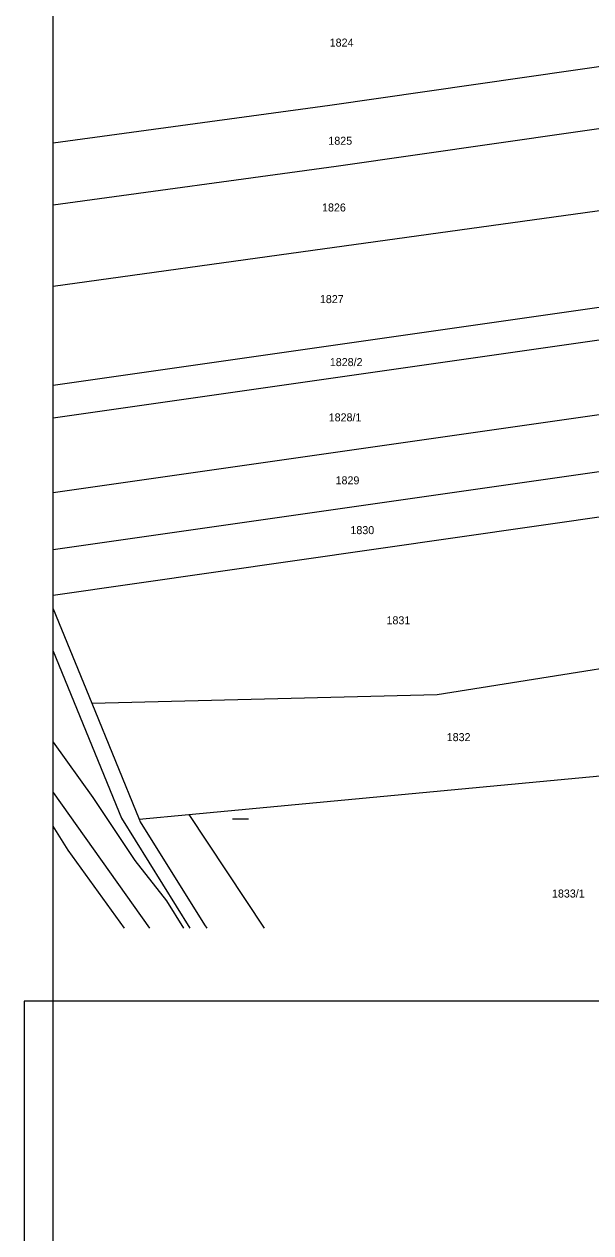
# Model space of a CAD drawing. Extents: x -601800 to -601487, y -1201912 to -1200862.
# Drawn here: x -601790.9 to -601649.2, y -1201385.7 to -1201083.7 of the extents above; entities that cross this region are included whole.
import ezdxf

# ---------------------------------------------------------------- set-up
doc = ezdxf.new("R2010")
doc.units = 0
for name, color, linetype in [('Hranice parcel', 7, 'Continuous'), ('Parcelní čísla', 7, 'Continuous'), ('u_strom', 7, 'Continuous'), ('x_rám', 7, 'Continuous')]:
    doc.layers.add(name, color=color, linetype=linetype)

msp = doc.modelspace()

# ---------------------------------------------------------------- linework, layer by layer
at = {"layer": 'Hranice parcel'}
for p, q in [((-601783.66, -1201173.9), (-601629.54, -1201151.87)), ((-601632.4, -1201160.49), (-601783.66, -1201182.11)), ((-601634.44, -1201179.47), (-601783.66, -1201200.8)), ((-601783.66, -1201214.97), (-601631.89, -1201193.28)), ((-601783.66, -1201226.33), (-601628.22, -1201204.11)), ((-601783.66, -1201229.79), (-601774, -1201253.38)), ((-601774, -1201253.38), (-601762.13, -1201282.35)), ((-601749.75, -1201281.18), (-601587.88, -1201265.89)), ((-601762.13, -1201282.35), (-601749.75, -1201281.18)), ((-601749.75, -1201281.18), (-601730.93, -1201309.6))]:
    msp.add_line(p, q, dxfattribs=at)
for points in [[(-601783.66, -1201113.35), (-601714.46, -1201103.92), (-601580.66, -1201084.64)], [(-601783.66, -1201128.79), (-601712.92, -1201119.14), (-601593.88, -1201102.11)], [(-601783.66, -1201149.13), (-601718.74, -1201140.14), (-601613.91, -1201125.63)], [(-601774, -1201253.38), (-601687.66, -1201251.2), (-601608.09, -1201238.51)], [(-601783.66, -1201240.35), (-601766.57, -1201282.06), (-601749.45, -1201309.6)], [(-601783.66, -1201263.06), (-601773.69, -1201276.89), (-601763.21, -1201292.63), (-601755.27, -1201302.75), (-601751.03, -1201309.6)], [(-601783.66, -1201275.7), (-601759.58, -1201309.6)], [(-601762.13, -1201282.35), (-601761.86, -1201283.01), (-601745.84, -1201308.76), (-601745.24, -1201309.6)], [(-601765.8, -1201309.6), (-601779.85, -1201290.08), (-601783.66, -1201284.08)]]:
    msp.add_lwpolyline(points, dxfattribs=at)
at = {"layer": 'u_strom'}
msp.add_lwpolyline([(-601790.89, -1201506.46), (-601590.84, -1201506.46), (-601590.84, -1201327.83), (-601790.89, -1201327.83)], close=True, dxfattribs=at)
at = {"layer": 'x_rám'}
msp.add_line((-601734.8, -1201282.35), (-601738.84, -1201282.35), dxfattribs=at)
msp.add_lwpolyline([(-601486.66, -1200862.35), (-601486.66, -1201912.35), (-601783.66, -1201912.35), (-601783.66, -1200862.35)], close=True, dxfattribs=at)

# ---------------------------------------------------------------- texts
at = {"layer": 'Parcelní čísla'}
for s, p in [('1824', (-601714.52, -1201089.27)), ('1825', (-601714.86, -1201113.8)), ('1826', (-601716.43, -1201130.48)), ('1827', (-601716.97, -1201153.38)), ('1828/2', (-601714.49, -1201169.12)), ('1828/1', (-601714.77, -1201182.93)), ('1829', (-601713.05, -1201198.67)), ('1830', (-601709.34, -1201211.11)), ('1831', (-601700.32, -1201233.64)), ('1832', (-601685.27, -1201262.84)), ('1833/1', (-601658.96, -1201301.92))]:
    msp.add_text(s, height=2, dxfattribs=at).set_placement(p)

doc.saveas('drawing.dxf')
